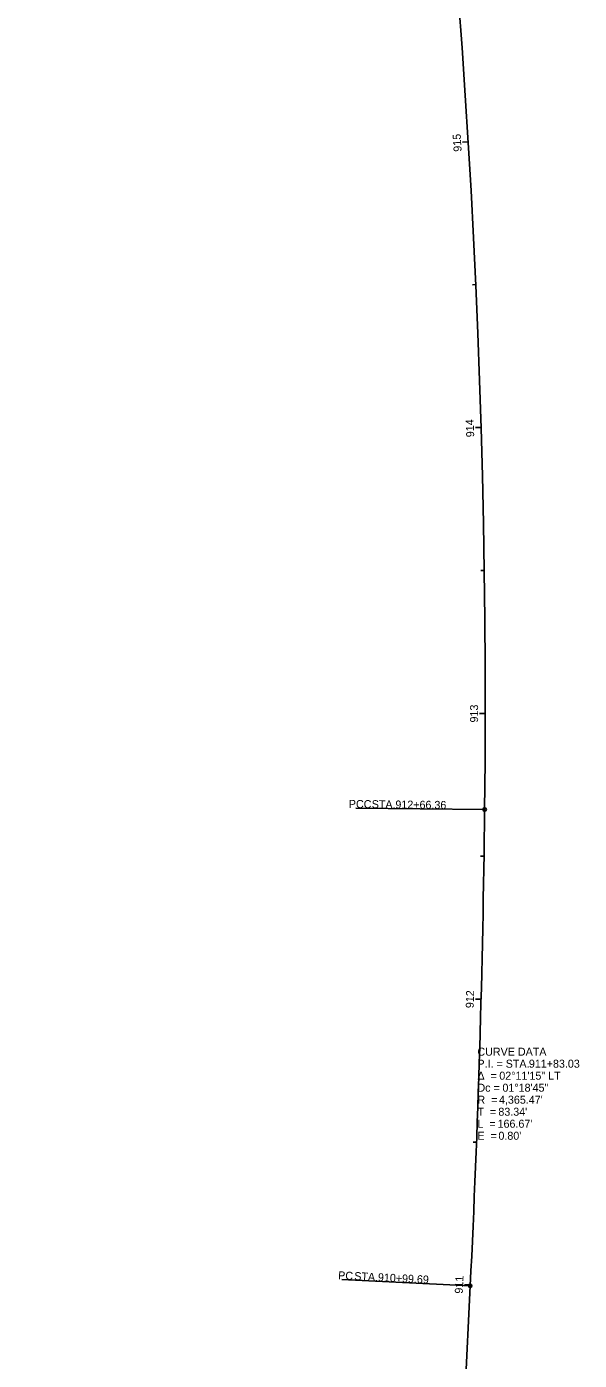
# Model space of a CAD drawing. Extents: x 145633 to 146120, y 414528 to 417535.
# Drawn here: x 145927.2 to 146120.5, y 415603.1 to 416069.5 of the extents above; entities that cross this region are included whole.
import ezdxf

# ---------------------------------------------------------------- set-up
doc = ezdxf.new("R2010")
doc.units = 0
for name, color, linetype in [('GE_X_Alignment', 7, 'Continuous'), ('GE_X_Alignment_100_Cardinal_Points', 7, 'Continuous'), ('GE_X_Alignment_100_Curve_Data', 7, 'Continuous'), ('GE_X_Alignment_100_Stations', 7, 'Continuous'), ('SC_Scratch3', 7, 'Continuous')]:
    doc.layers.add(name, color=color, linetype=linetype)

msp = doc.modelspace()

# ---------------------------------------------------------------- linework, layer by layer
at = {"layer": 'GE_X_Alignment'}
msp.add_line((146028.12, 414530.76), (146082.33, 415629.12), dxfattribs=at)
for centre, radius, start, end in [((142813.52, 415832.16), 3274.05, 359.36198, 18.00643), ((141722.17, 415844.31), 4365.47, 357.17448, 359.36198)]:
    msp.add_arc(centre, radius, start, end, dxfattribs=at)
at = {"layer": 'GE_X_Alignment_100_Cardinal_Points'}
for p, q in [((146087.37, 415795.7), (146042.37, 415796.2)), ((146082.33, 415629.12), (146037.39, 415631.33))]:
    msp.add_line(p, q, dxfattribs=at)
for centre in [(146087.37, 415795.7), (146082.33, 415629.12)]:
    msp.add_circle(centre, 0.6, dxfattribs=at)
at = {"layer": 'GE_X_Alignment_100_Stations'}
for p, q in [((146081.64, 416029.22), (146079.64, 416029.1)), ((146084.26, 415979.29), (146083.07, 415979.24)), ((146086.13, 415929.32), (146084.13, 415929.27)), ((146087.23, 415879.34), (146086.03, 415879.32)), ((146087.57, 415829.34), (146085.57, 415829.34)), ((146087.16, 415779.34), (146085.96, 415779.36)), ((146086.13, 415729.35), (146084.13, 415729.4)), ((146084.52, 415679.38), (146083.32, 415679.42)), ((146082.35, 415629.43), (146080.35, 415629.52))]:
    msp.add_line(p, q, dxfattribs=at)
at = {"layer": 'SC_Scratch3'}
for centre, radius, start, end in [((142813.52, 415832.16), 3274.05, 359.36198, 18.00643), ((141722.17, 415844.31), 4365.47, 357.17448, 359.36198)]:
    msp.add_arc(centre, radius, start, end, dxfattribs=at)

# ---------------------------------------------------------------- texts
at = {"layer": 'GE_X_Alignment_100_Cardinal_Points'}
for s, rotation, p in [('PCC', 359.362, (146039.87, 415796.27)), (' STA. ', 359.362, (146046.83, 415796.19)), ('912+66.36', 359.362, (146056.15, 415796.08)), ('PC', 357.1745, (146036.09, 415631.43)), (' STA. ', 357.1745, (146040.69, 415631.21)), ('910+99.69', 357.1745, (146050, 415630.75))]:
    msp.add_text(s, height=2.8, rotation=rotation, dxfattribs=at).set_placement(p)
at = {"layer": 'GE_X_Alignment_100_Curve_Data'}
for s, p in [('CURVE DATA', (146084.85, 415709.61)), ('P.I. = STA. ', (146084.85, 415705.41)), ('911+83.03', (146102.84, 415705.41)), ('Δ  = ', (146084.85, 415701.21)), ('02°11\'15" LT', (146092.5, 415701.21)), ('Dc = ', (146084.85, 415697.01)), ('01°18\'45"', (146093.59, 415697.01)), ('T  = ', (146084.85, 415688.61)), ('R  = ', (146084.85, 415692.81)), ("83.34'", (146092.17, 415688.61)), ("4,365.47'", (146092.39, 415692.81)), ('L  = ', (146084.85, 415684.41)), ("166.67'", (146091.89, 415684.41)), ('E  = ', (146084.85, 415680.21)), ("0.80'", (146092.19, 415680.21))]:
    msp.add_text(s, height=2.8, dxfattribs=at).set_placement(p)
at = {"layer": 'GE_X_Alignment_100_Stations'}
for s, rotation, p in [('915', 93.4507, (146079.33, 416025.87)), ('914', 91.7007, (146083.73, 415925.97)), ('913', 89.9507, (146085.07, 415826.14)), ('912', 88.491, (146083.54, 415726.21)), ('911', 87.1785, (146079.69, 415626.33))]:
    msp.add_text(s, height=2.8, rotation=rotation, dxfattribs=at).set_placement(p)

doc.saveas('drawing.dxf')
